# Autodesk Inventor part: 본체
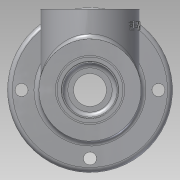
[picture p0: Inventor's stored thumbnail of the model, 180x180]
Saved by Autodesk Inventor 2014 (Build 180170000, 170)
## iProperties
Created: 2016-08
Part Number: 본체
Material: Aluminum 6061
Document SubType Name: Modeling
Designer: user
Density: 2.71 g/cm^3
Appearance: Aluminum - Flat
Mass: 728.372 g
Surface Area: 615.733 cm^2
Volume: 268.772 cm^3
Author: user
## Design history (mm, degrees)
sketch "Sketch1"
  geometry: L1 (-56, 0)-(59, 0); L2 (-56, 0)-(-56, 31); L3 (-56, 31)-(46, 31); L4 (46, 31)-(46, 50); L5 (46, 50)-(56, 50); L6 (56, 50)-(56, 31); L7 (56, 31)-(59, 31); L8 (59, 31)-(59, 0); 1 further point
  constraints: 16 end point, 4 vertical, 3 horizontal, 1 collinear, 1 point on line
  dimensions: "d0" = 115 distance of L1.start L1.end; "d1" = 3 distance between parallel lines of L8 L6; "d2" = 13 distance between parallel lines of L8 L4; "d3" = 62 diameter of L3 L1; "d4" = 56 distance from line of point (0, 0) L2; "d5" = 100 diameter of L5 L1
revolve "Revolution1" sketch "Sketch1" stored, may be unused: angle "d6" = 90 deg
workplane "Work Plane1"
sketch "Sketch2"
  geometry: C1 r 30 at (0, 0); 1 further point
  constraints: 1 centre point, 1 coincident
  dimensions: "d8" = 60 diameter of C1
extrude "Extrusion1" join sketch "Sketch2" stored distance "d9" = 10; taper "d10" = 0 deg
hole "Hole1" diameter "d13" = 38; stored, may be unused: countersink angle "d17" = 90 deg, drill point angle "d19" = 0 deg; dims "d11" = 10, "d12" = 10, "d14" = 6, "d15" = 4, "d16" = 2, "d18" = 49
sketch "Sketch3"
  geometry: L1 (56, -31)-(-46, -31) reference; L2 (56, 31)-(56, -31) reference; L3 (-59, 31)-(-59, -31) reference; L4 (73.925, 0)-(-73.925, 0); L5 (-45, 16.5)-(-45, 16); L6 (-37.7, 13.393)-(-37.7, 12.5); L7 (-45, 16)-(-59, 21); L8 (-45, 12.5)-(-37.7, 12.5); L9 (-37.7, 10)-(-35, 10); L10 (-30, 16.5)-(-35, 16.5); L11 (-45, 16)-(-45, 0); L12 (-37.7, 12.5)-(-37.7, 0); L13 (-35, 16.5)-(-35, 0); L14 (-30, 16.5)-(-30, 0); L15 (-59, 21)-(-59, 0); 2 further points
  constraints: 24 end point, 13 point on line, 9 parallel, 4 horizontal, 2 midpoint, 1 coincident
  dimensions: "d20" = 14 distance between parallel lines of L3 L5; "d24" = 147.85067 distance of L4.start L4.end; "d25" = 42 diameter of L7.end L4; "d26" = 32 diameter of L5.end L4; "d27" = 25 diameter of L8 L4; "d28" = 20 diameter of L9 L4; "d29" = 33 diameter of L10 L4; "d30" = 5 distance between parallel lines of L13 L14; "d31" = 2.7 distance between parallel lines of L12 L13; "d32" = 7.3 distance between parallel lines of L11 L12
revolve "Revolution2" sketch "Sketch3" stored, may be unused: angle "d33" = 90 deg
hole "Hole2" diameter "d36" = 42; stored, may be unused: countersink angle "d40" = 90 deg, drill point angle "d42" = 0 deg; dims "d34" = 10, "d35" = 10, "d37" = 6, "d38" = 4, "d39" = 2, "d41" = 9
hole "Hole3" diameter "d45" = 48; stored, may be unused: countersink angle "d49" = 90 deg, drill point angle "d51" = 0 deg; dims "d43" = 10, "d44" = 10, "d46" = 6, "d47" = 4, "d48" = 2, "d50" = 3
sketch "Sketch4"
  geometry: C1 r 24 at (0, 0) reference; C2 r 20 at (0, 0)
  constraints: 1 centre point, 1 coincident
  dimensions: "d52" = 40 diameter of C2
extrude "Extrusion2" cut sketch "Sketch4" distance "d53" = 9; taper "d54" = 0 deg
sketch "Sketch5"
  geometry: L1 (35, 20)-(35, -20) reference; L2 (35, 0)-(-35, 0); L3 (30, 18.5)-(30, 0); L4 (31.75, 18.5)-(31.75, 0); L5 (-30, 17.5)-(-30, 0); L6 (35, 17.5)-(31.75, 17.5); L7 (31.75, 18.5)-(30, 18.5); L8 (19, 26)-(-19, 26); L9 (-19, 26)-(-19, 0); L10 (19, 0)-(19, 26); L11 (30, 17.5)-(19, 17.5); L12 (-19, 17.5)-(-30, 17.5); L13 (35, 17.5)-(35, 0); 2 further points
  constraints: 24 end point, 10 point on line, 3 parallel, 2 collinear, 2 midpoint, 1 coincident, 1 horizontal
  dimensions: "d55" = 5 distance between parallel lines of L3 L1; "d56" = 1.75 distance between parallel lines of L3 L4; "d57" = 60 distance between parallel lines of L5 L3; "d59" = 37 diameter of L7 L2; "d60" = 38 distance between parallel lines of L9 L10; "d61" = 52 diameter of L8 L2; "d62" = 19 distance from line of point (0, 0) L10; "d63" = 11 distance between parallel lines of L10 L3 (derived); "d64" = 35 diameter of L12 L2
revolve "Revolution3" sketch "Sketch5" stored, may be unused: angle "d65" = 90 deg
sketch "Sketch6"
  geometry: C1 r 19 at (0, 0) reference; 1 further point
  constraints: 1 vertical alignment
  dimensions: "d66" = 24 distance of C1.centre point (0, 24)
hole "Hole4" sketch "Sketch6" at (0, 24) diameter "d67" = 3.242; stored, may be unused: countersink angle "d71" = 90 deg, drill point angle "d73" = 118 deg; dims "d68" = 8, "d69" = 4, "d70" = 2, "d72" = 10
pattern_circular "Circular Pattern1" dims angle "d75" = 360 deg
sketch "Sketch7"
  geometry: C1 r 31 at (0, 0) reference; 1 further point
  constraints: 1 vertical alignment
  dimensions: "d77" = 41.5 distance of C1.centre point (0, 41.5)
hole "Hole5" sketch "Sketch7" at (0, 41.5) diameter "d78" = 8; stored, may be unused: countersink angle "d82" = 90 deg, drill point angle "d84" = 0 deg; dims "d79" = 8, "d80" = 4, "d81" = 2, "d83" = 10
pattern_circular "Circular Pattern2" dims angle "d86" = 360 deg
thread "Thread1" dims "d88" = 10, "d89" = 0
chamfer "Chamfer1" distance "d90" = 1; stored, may be unused: second distance "d91" = 2, angle "d92" = 45 deg
workplane "Work Plane2"
sketch "Sketch8"
  geometry: L1 (-56, -31)-(-56, 31) reference; L2 (-30, 49)-(30, 49) reference; 2 further points
  constraints: 1 other
  dimensions: "d94" = 56 distance from line of point (0, 39) L1; "d95" = 10 distance from line of point (0, 39) L2
emboss "Emboss1" sketch "Sketch8" dims "d96" = 0.5, "d97" = 0
fillet "Fillet1" dims "d98" = 3
fillet "Fillet2" dims "d99" = 3
fillet "Fillet4" dims "d101" = 0.3
fillet "Fillet5" dims "d105" = 3
fillet "Fillet6" dims "d106" = 0.3
fillet "Fillet8" dims "d108" = 3
fillet "Fillet9" dims "d109" = 3
chamfer "Chamfer3" distance "d110" = 0.7; stored, may be unused: second distance "d111" = 2, angle "d112" = 30 deg
body "Solid1"
other parameters: "d7" = 49, "d58" = 35, "d93" = -32
